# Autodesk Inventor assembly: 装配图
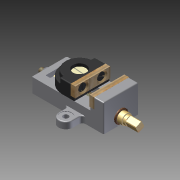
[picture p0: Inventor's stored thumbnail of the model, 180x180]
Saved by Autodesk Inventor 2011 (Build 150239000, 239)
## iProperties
Created: 2013-12
Part Number: 装配图
Document SubType Name: Assembly
Designer: Administrator
Author: Administrator
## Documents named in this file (11)
- F:\Mr.L\学习\CAD\虎钳\装配图.iam
- F:\Mr.L\学习\CAD\虎钳\钳座.ipt
- F:\Mr.L\学习\CAD\虎钳\垫圈.ipt
- F:\Mr.L\学习\CAD\虎钳\方块螺母.ipt
- F:\Mr.L\学习\CAD\虎钳\护口板.ipt
- F:\Mr.L\学习\CAD\虎钳\活动钳块.ipt
- F:\Mr.L\学习\CAD\虎钳\螺钉 GB_T 68 M8 x 12.ipt
- F:\Mr.L\学习\CAD\虎钳\螺钉.ipt
- F:\Mr.L\学习\CAD\虎钳\螺杆.ipt
- F:\Mr.L\学习\CAD\虎钳\螺母 GB_T 6170 M10.ipt
- F:\Mr.L\学习\CAD\虎钳\平垫圈 GB_T 97.1 10.ipt
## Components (14 placed, 10 different names)
1. 钳座:1 — 插入:1, 插入:3, 配合:1, 表面齐平:1, 表面齐平:2, 配合:7, 表面齐平:4
2. 垫圈:1 — 插入:1, 插入:2
3. 护口板:1 — 配合:1, 表面齐平:1, 表面齐平:2, 配合:8, 配合:9, 相切:2, 配合:11, 相切:4
4. 活动钳块:1 — 配合:2, 配合:3, 表面齐平:3, 配合:7, 表面齐平:4, 配合:12
5. 螺钉 GB_T 68 M8 x 12:1 — 配合:4, 配合:5, 配合:6, 相切:1
6. 螺钉:1 — 插入:5
7. 螺杆:1 — 插入:2, 配合:13
8. 螺母 GB_T 6170 M10:1 — 插入:4
9. 平垫圈 GB_T 97.1 10:1 — 插入:3, 插入:4
10. 护口板:2 — 配合:2, 配合:3, 表面齐平:3, 配合:4, 配合:5, 配合:6, 相切:1, 配合:8, 配合:10, 相切:3
11. 螺钉 GB_T 68 M8 x 12:2 — 配合:11, 相切:4
12. 螺钉 GB_T 68 M8 x 12:3 — 配合:10, 相切:3
13. 螺钉 GB_T 68 M8 x 12:4 — 配合:9, 相切:2
14. 方块螺母:1 — 配合:12, 配合:13, 插入:5
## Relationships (26: Mate 13, Insert 5, Flush 4, Tangent 4)
- 插入:1 [Insert]: 钳座:1 ↔ 垫圈:1
- 插入:2 [Insert]: 垫圈:1 ↔ 螺杆:1
- 插入:3 [Insert]: 钳座:1 ↔ 平垫圈 GB_T 97.1 10:1
- 插入:4 [Insert]: 螺母 GB_T 6170 M10:1 ↔ 平垫圈 GB_T 97.1 10:1
- 配合:1 [Mate]: 钳座:1 ↔ 护口板:1
- 表面齐平:1 [Flush]: 钳座:1 ↔ 护口板:1
- 表面齐平:2 [Flush]: 钳座:1 ↔ 护口板:1
- 配合:2 [Mate]: 活动钳块:1 ↔ 护口板:2
- 配合:3 [Mate]: 活动钳块:1 ↔ 护口板:2
- 表面齐平:3 [Flush]: 活动钳块:1 ↔ 护口板:2
- 配合:4 [Mate]: 螺钉 GB_T 68 M8 x 12:1 ↔ 护口板:2
- 配合:5 [Mate]: 螺钉 GB_T 68 M8 x 12:1 ↔ 护口板:2
- 配合:6 [Mate]: 螺钉 GB_T 68 M8 x 12:1 ↔ 护口板:2
- 相切:1 [Tangent]: 螺钉 GB_T 68 M8 x 12:1 ↔ 护口板:2
- 配合:7 [Mate]: 钳座:1 ↔ 活动钳块:1
- 表面齐平:4 [Flush]: 钳座:1 ↔ 活动钳块:1
- 配合:8 [Mate]: 护口板:1 ↔ 护口板:2
- 配合:9 [Mate]: 护口板:1 ↔ 螺钉 GB_T 68 M8 x 12:4
- 相切:2 [Tangent]: 护口板:1 ↔ 螺钉 GB_T 68 M8 x 12:4
- 配合:10 [Mate]: 护口板:2 ↔ 螺钉 GB_T 68 M8 x 12:3
- 相切:3 [Tangent]: 护口板:2 ↔ 螺钉 GB_T 68 M8 x 12:3
- 配合:11 [Mate]: 护口板:1 ↔ 螺钉 GB_T 68 M8 x 12:2
- 相切:4 [Tangent]: 护口板:1 ↔ 螺钉 GB_T 68 M8 x 12:2
- 配合:12 [Mate]: 活动钳块:1 ↔ 方块螺母:1
- 配合:13 [Mate]: 螺杆:1 ↔ 方块螺母:1
- 插入:5 [Insert]: 螺钉:1 ↔ 方块螺母:1
